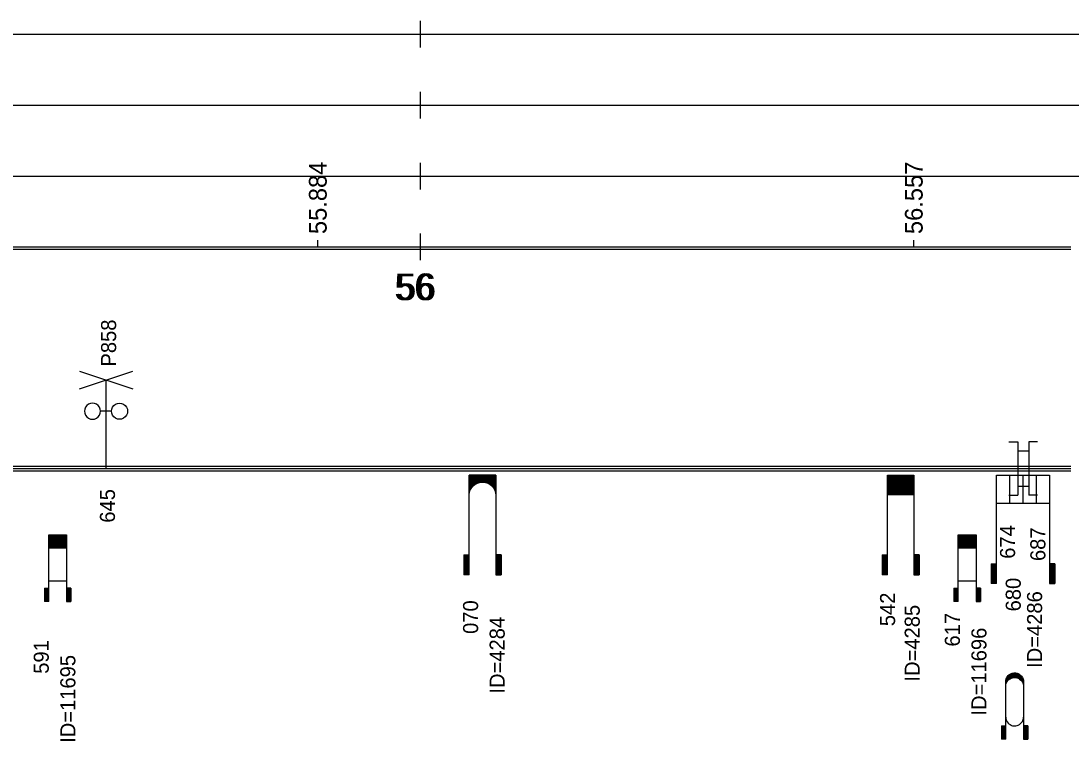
# Model space of a CAD drawing. Extents: x 2 to 10148, y 0 to 380.
# Drawn here: x 5856.4 to 5974.9, y 94.2 to 175.5 of the extents above; entities that cross this region are included whole.
import ezdxf

# ---------------------------------------------------------------- set-up
doc = ezdxf.new("R2010")
doc.units = 0
for name, color, linetype in [('CARA_S_OBJEKTY', 7, 'Continuous'), ('L_OBJEKTY_TEXT', 7, 'Continuous'), ('L_OBJEKTY_TVAR', 7, 'Continuous'), ('OBJEKTY_TEXT', 7, 'Continuous'), ('OBJEKTY_TVAR', 7, 'Continuous'), ('RYCHL_RASTR', 7, 'Continuous'), ('RYCHL_STAN', 7, 'Continuous'), ('STANIC_ZMEN_V', 7, 'Continuous')]:
    doc.layers.add(name, color=color, linetype=linetype)

msp = doc.modelspace()

# ---------------------------------------------------------------- linework, layer by layer
at = {"layer": 'CARA_S_OBJEKTY'}
for p, q in [((5128.6, 125.25), (5974.91, 125.25)), ((5128.6, 125), (5974.91, 125)), ((5128.6, 124.75), (5974.91, 124.75))]:
    msp.add_line(p, q, dxfattribs=at)
at = {"layer": 'L_OBJEKTY_TVAR'}
for p, q in [((5967.91, 128), (5968.91, 128)), ((5968.91, 128), (5968.91, 122)), ((5970.14, 128), (5970.14, 122)), ((5971.14, 128), (5970.14, 128)), ((5968.91, 127), (5970.14, 127)), ((5968.91, 123), (5970.14, 123)), ((5967.91, 122), (5968.91, 122)), ((5971.14, 122), (5970.14, 122))]:
    msp.add_line(p, q, dxfattribs=at)
at = {"layer": 'OBJEKTY_TVAR'}
for p, q in [((5863.03, 134), (5869.03, 136)), ((5863.03, 136), (5869.03, 134)), ((5866.03, 125), (5866.03, 135)), ((5863.6, 131.7), (5863.57, 131.46)), ((5863.69, 131.92), (5863.6, 131.7)), ((5863.84, 132.11), (5863.69, 131.92)), ((5864.03, 132.25), (5863.84, 132.11)), ((5864.25, 132.34), (5864.03, 132.25)), ((5864.48, 132.38), (5864.25, 132.34)), ((5864.72, 132.34), (5864.48, 132.38)), ((5864.94, 132.25), (5864.72, 132.34)), ((5865.13, 132.11), (5864.94, 132.25)), ((5865.27, 131.92), (5865.13, 132.11)), ((5865.36, 131.7), (5865.27, 131.92)), ((5865.39, 131.46), (5865.36, 131.7)), ((5866.63, 131.46), (5866.66, 131.7)), ((5866.66, 131.7), (5866.75, 131.92)), ((5866.75, 131.92), (5866.89, 132.11)), ((5866.89, 132.11), (5867.08, 132.25)), ((5867.08, 132.25), (5867.3, 132.34)), ((5867.3, 132.34), (5867.54, 132.38)), ((5867.54, 132.38), (5867.77, 132.34)), ((5867.77, 132.34), (5867.99, 132.25)), ((5867.99, 132.25), (5868.18, 132.11)), ((5868.18, 132.11), (5868.33, 131.92)), ((5868.33, 131.92), (5868.42, 131.7)), ((5868.42, 131.7), (5868.45, 131.46)), ((5863.57, 131.46), (5863.6, 131.23)), ((5863.6, 131.23), (5863.69, 131.01)), ((5863.69, 131.01), (5863.84, 130.82)), ((5863.84, 130.82), (5864.03, 130.67)), ((5864.03, 130.67), (5864.25, 130.58)), ((5864.25, 130.58), (5864.48, 130.55)), ((5864.48, 130.55), (5864.72, 130.58)), ((5864.72, 130.58), (5864.94, 130.67)), ((5864.94, 130.67), (5865.13, 130.82)), ((5865.13, 130.82), (5865.27, 131.01)), ((5865.27, 131.01), (5865.36, 131.23)), ((5865.36, 131.23), (5865.39, 131.46)), ((5866.63, 131.46), (5865.39, 131.46)), ((5866.66, 131.23), (5866.63, 131.46)), ((5866.75, 131.01), (5866.66, 131.23)), ((5866.89, 130.82), (5866.75, 131.01)), ((5867.08, 130.67), (5866.89, 130.82)), ((5867.3, 130.58), (5867.08, 130.67)), ((5867.54, 130.55), (5867.3, 130.58)), ((5867.77, 130.58), (5867.54, 130.55)), ((5867.99, 130.67), (5867.77, 130.58)), ((5868.18, 130.82), (5867.99, 130.67)), ((5868.33, 131.01), (5868.18, 130.82)), ((5868.42, 131.23), (5868.33, 131.01)), ((5868.45, 131.46), (5868.42, 131.23)), ((5907, 113), (5907, 124.25)), ((5910, 124.25), (5907, 124.25)), ((5907, 124.17), (5910, 124.17)), ((5907, 124.1), (5910, 124.1)), ((5907, 124.02), (5910, 124.02)), ((5907, 123.95), (5910, 123.95)), ((5907, 123.87), (5910, 123.87)), ((5907, 123.8), (5910, 123.8)), ((5907, 123.72), (5910, 123.72)), ((5907, 123.65), (5910, 123.65)), ((5907, 123.57), (5910, 123.57)), ((5907, 123.5), (5910, 123.5)), ((5907, 123.42), (5908.16, 123.42)), ((5907, 123.35), (5907.92, 123.35)), ((5907, 123.27), (5907.77, 123.27)), ((5907.64, 123.19), (5907.77, 123.27)), ((5907.77, 123.27), (5907.92, 123.35)), ((5907.92, 123.35), (5908.16, 123.42)), ((5908.16, 123.42), (5908.37, 123.46)), ((5908.37, 123.46), (5908.62, 123.46)), ((5908.62, 123.46), (5908.76, 123.44)), ((5908.76, 123.44), (5908.84, 123.42)), ((5908.84, 123.42), (5910, 123.42)), ((5908.84, 123.42), (5909.08, 123.35)), ((5909.08, 123.35), (5910, 123.35)), ((5909.08, 123.35), (5909.23, 123.27)), ((5909.23, 123.27), (5910, 123.27)), ((5909.23, 123.27), (5909.35, 123.2)), ((5910, 124.25), (5910, 113)), ((5954.19, 124.25), (5957.19, 124.25)), ((5954.19, 113), (5954.19, 124.25)), ((5954.19, 124.17), (5957.19, 124.17)), ((5954.19, 124.1), (5957.19, 124.1)), ((5954.19, 124.02), (5957.19, 124.02)), ((5954.19, 123.95), (5957.19, 123.95)), ((5954.19, 123.87), (5957.19, 123.87)), ((5954.19, 123.8), (5957.19, 123.8)), ((5954.19, 123.72), (5957.19, 123.72)), ((5954.19, 123.65), (5957.19, 123.65)), ((5954.19, 123.57), (5957.19, 123.57)), ((5954.19, 123.5), (5957.19, 123.5)), ((5954.19, 123.42), (5957.19, 123.42)), ((5954.19, 123.35), (5957.19, 123.35)), ((5954.19, 123.27), (5957.19, 123.27)), ((5957.19, 124.25), (5957.19, 113)), ((5966.5, 112), (5966.5, 124.25)), ((5966.5, 124.25), (5972.5, 124.25)), ((5968, 121.07), (5968, 124.25)), ((5969.5, 121.07), (5969.5, 124.25)), ((5971, 121.07), (5971, 124.25)), ((5972.5, 124.25), (5972.5, 112)), ((5907, 123.2), (5907.65, 123.2)), ((5907, 123.12), (5907.55, 123.12)), ((5907, 123.05), (5907.46, 123.05)), ((5907, 122.97), (5907.39, 122.97)), ((5907, 122.9), (5907.33, 122.9)), ((5907, 122.82), (5907.27, 122.82)), ((5907, 122.75), (5907.22, 122.75)), ((5907, 122.67), (5907.18, 122.67)), ((5907, 122.6), (5907.14, 122.6)), ((5907, 122.52), (5907.11, 122.52)), ((5907, 122.45), (5907.08, 122.45)), ((5907, 122.37), (5907.06, 122.37)), ((5907, 122.3), (5907.04, 122.3)), ((5907, 122.22), (5907.02, 122.22)), ((5907, 122.15), (5907.01, 122.15)), ((5907, 121.97), (5907.01, 122.11)), ((5907.01, 122.11), (5907.03, 122.28)), ((5907.03, 122.28), (5907.08, 122.46)), ((5907.08, 122.46), (5907.15, 122.61)), ((5907.15, 122.61), (5907.22, 122.75)), ((5907.22, 122.75), (5907.33, 122.9)), ((5907.33, 122.9), (5907.46, 123.05)), ((5907.46, 123.05), (5907.54, 123.12)), ((5907.54, 123.12), (5907.64, 123.19)), ((5909.35, 123.2), (5910, 123.2)), ((5909.35, 123.2), (5909.45, 123.12)), ((5909.45, 123.12), (5910, 123.12)), ((5909.45, 123.12), (5909.54, 123.05)), ((5909.54, 123.05), (5910, 123.05)), ((5909.54, 123.05), (5909.61, 122.97)), ((5909.61, 122.97), (5910, 122.97)), ((5909.61, 122.97), (5909.67, 122.9)), ((5909.67, 122.9), (5909.99, 122.9)), ((5909.67, 122.9), (5909.73, 122.82)), ((5909.73, 122.82), (5910, 122.82)), ((5909.73, 122.82), (5909.82, 122.67)), ((5909.78, 122.75), (5910, 122.75)), ((5909.82, 122.67), (5910, 122.67)), ((5909.82, 122.67), (5909.89, 122.52)), ((5909.86, 122.6), (5910, 122.6)), ((5909.89, 122.52), (5910, 122.52)), ((5909.89, 122.52), (5909.94, 122.37)), ((5909.92, 122.45), (5910, 122.45)), ((5909.94, 122.37), (5910, 122.37)), ((5909.94, 122.37), (5909.98, 122.22)), ((5909.96, 122.3), (5910, 122.3)), ((5909.98, 122.22), (5910, 122.22)), ((5909.98, 122.22), (5910, 121.97)), ((5909.99, 122.15), (5910, 122.15)), ((5954.19, 123.2), (5957.19, 123.2)), ((5954.19, 123.12), (5957.19, 123.12)), ((5954.19, 123.05), (5957.19, 123.05)), ((5954.19, 122.97), (5957.19, 122.97)), ((5954.19, 122.9), (5957.19, 122.9)), ((5954.19, 122.82), (5957.19, 122.82)), ((5954.19, 122.75), (5957.19, 122.75)), ((5954.19, 122.67), (5957.19, 122.67)), ((5954.19, 122.6), (5957.19, 122.6)), ((5954.19, 122.52), (5957.19, 122.52)), ((5954.19, 122.45), (5957.19, 122.45)), ((5954.19, 122.37), (5957.19, 122.37)), ((5954.19, 122.3), (5957.19, 122.3)), ((5954.19, 122.22), (5957.19, 122.22)), ((5954.19, 122.15), (5957.19, 122.15)), ((5954.19, 122.07), (5957.19, 122.07)), ((5966.5, 121.07), (5972.5, 121.07)), ((5859.55, 110), (5859.55, 117.5)), ((5859.55, 117.5), (5861.55, 117.5)), ((5859.55, 117.45), (5861.55, 117.45)), ((5859.55, 117.4), (5861.55, 117.4)), ((5859.55, 117.35), (5861.55, 117.35)), ((5861.55, 117.5), (5861.55, 110)), ((5962.19, 110), (5962.19, 117.5)), ((5962.19, 117.5), (5964.19, 117.5)), ((5962.19, 117.45), (5964.19, 117.45)), ((5962.19, 117.4), (5964.19, 117.4)), ((5962.19, 117.35), (5964.19, 117.35)), ((5964.19, 117.5), (5964.19, 110)), ((5859.55, 117.3), (5861.55, 117.3)), ((5859.55, 117.25), (5861.55, 117.25)), ((5859.55, 117.2), (5861.55, 117.2)), ((5859.55, 117.15), (5861.55, 117.15)), ((5859.55, 117.1), (5861.55, 117.1)), ((5859.55, 117.05), (5861.55, 117.05)), ((5859.55, 117), (5861.55, 117)), ((5859.55, 116.95), (5861.55, 116.95)), ((5859.55, 116.9), (5861.55, 116.9)), ((5859.55, 116.85), (5861.55, 116.85)), ((5859.55, 116.8), (5861.55, 116.8)), ((5859.55, 116.75), (5861.55, 116.75)), ((5859.55, 116.7), (5861.55, 116.7)), ((5859.55, 116.65), (5861.55, 116.65)), ((5859.55, 116.6), (5861.55, 116.6)), ((5859.55, 116.55), (5861.55, 116.55)), ((5859.55, 116.5), (5861.55, 116.5)), ((5859.55, 116.45), (5861.55, 116.45)), ((5859.55, 116.4), (5861.55, 116.4)), ((5859.55, 116.35), (5861.55, 116.35)), ((5859.55, 116.3), (5861.55, 116.3)), ((5859.55, 116.25), (5861.55, 116.25)), ((5859.55, 116.2), (5861.55, 116.2)), ((5859.55, 116.15), (5861.55, 116.15)), ((5962.19, 117.3), (5964.19, 117.3)), ((5962.19, 117.25), (5964.19, 117.25)), ((5962.19, 117.2), (5964.19, 117.2)), ((5962.19, 117.15), (5964.19, 117.15)), ((5962.19, 117.1), (5964.19, 117.1)), ((5962.19, 117.05), (5964.19, 117.05)), ((5962.19, 117), (5964.19, 117)), ((5962.19, 116.95), (5964.19, 116.95)), ((5962.19, 116.9), (5964.19, 116.9)), ((5962.19, 116.85), (5964.19, 116.85)), ((5962.19, 116.8), (5964.19, 116.8)), ((5962.19, 116.75), (5964.19, 116.75)), ((5962.19, 116.7), (5964.19, 116.7)), ((5962.19, 116.65), (5964.19, 116.65)), ((5962.19, 116.6), (5964.19, 116.6)), ((5962.19, 116.55), (5964.19, 116.55)), ((5962.19, 116.5), (5964.19, 116.5)), ((5962.19, 116.45), (5964.19, 116.45)), ((5962.19, 116.4), (5964.19, 116.4)), ((5962.19, 116.35), (5964.19, 116.35)), ((5962.19, 116.3), (5964.19, 116.3)), ((5962.19, 116.25), (5964.19, 116.25)), ((5962.19, 116.2), (5964.19, 116.2)), ((5962.19, 116.15), (5964.19, 116.15)), ((5859.55, 116.1), (5861.55, 116.1)), ((5859.55, 116.05), (5861.55, 116.05)), ((5906.4, 115.25), (5907, 115.25)), ((5906.4, 115.25), (5906.4, 113)), ((5906.47, 115.25), (5906.47, 113)), ((5906.55, 115.25), (5906.55, 113)), ((5906.62, 115.25), (5906.62, 113)), ((5906.7, 115.25), (5906.7, 113)), ((5906.77, 115.25), (5906.77, 113)), ((5906.85, 115.25), (5906.85, 113)), ((5906.92, 115.25), (5906.92, 113)), ((5910.6, 115.25), (5910, 115.25)), ((5910.08, 115.25), (5910.08, 113)), ((5910.15, 115.25), (5910.15, 113)), ((5910.23, 115.25), (5910.23, 113)), ((5910.3, 115.25), (5910.3, 113)), ((5910.38, 115.25), (5910.38, 113)), ((5910.45, 115.25), (5910.45, 113)), ((5910.53, 115.25), (5910.53, 113)), ((5910.6, 115.25), (5910.6, 113)), ((5953.59, 115.25), (5953.59, 113)), ((5953.59, 115.25), (5954.19, 115.25)), ((5953.66, 115.25), (5953.66, 113)), ((5953.74, 115.25), (5953.74, 113)), ((5953.81, 115.25), (5953.81, 113)), ((5953.89, 115.25), (5953.89, 113)), ((5953.96, 115.25), (5953.96, 113)), ((5954.04, 115.25), (5954.04, 113)), ((5954.11, 115.25), (5954.11, 113)), ((5957.79, 115.25), (5957.19, 115.25)), ((5957.27, 115.25), (5957.27, 113)), ((5957.34, 115.25), (5957.34, 113)), ((5957.42, 115.25), (5957.42, 113)), ((5957.49, 115.25), (5957.49, 113)), ((5957.57, 115.25), (5957.57, 113)), ((5957.64, 115.25), (5957.64, 113)), ((5957.72, 115.25), (5957.72, 113)), ((5957.79, 115.25), (5957.79, 113)), ((5962.19, 116.1), (5964.19, 116.1)), ((5962.19, 116.05), (5964.19, 116.05)), ((5965.9, 114.25), (5965.9, 112)), ((5965.9, 114.25), (5966.5, 114.25)), ((5965.97, 114.25), (5965.97, 112)), ((5966.05, 114.25), (5966.05, 112)), ((5966.12, 114.25), (5966.12, 112)), ((5966.2, 114.25), (5966.2, 112)), ((5966.27, 114.25), (5966.27, 112)), ((5966.35, 114.25), (5966.35, 112)), ((5966.42, 114.25), (5966.42, 112)), ((5973.1, 114.25), (5972.5, 114.25)), ((5972.58, 114.25), (5972.58, 112)), ((5972.65, 114.25), (5972.65, 112)), ((5972.73, 114.25), (5972.73, 112)), ((5972.8, 114.25), (5972.8, 112)), ((5972.88, 114.25), (5972.88, 112)), ((5972.95, 114.25), (5972.95, 112)), ((5973.03, 114.25), (5973.03, 112)), ((5973.1, 114.25), (5973.1, 112)), ((5907, 113), (5906.4, 113)), ((5910, 113), (5910.6, 113)), ((5954.19, 113), (5953.59, 113)), ((5957.19, 113), (5957.79, 113)), ((5859.05, 111.5), (5859.55, 111.5)), ((5859.05, 111.5), (5859.05, 110)), ((5859.1, 111.5), (5859.1, 110)), ((5859.15, 111.5), (5859.15, 110)), ((5859.2, 111.5), (5859.2, 110)), ((5859.25, 111.5), (5859.25, 110)), ((5859.3, 111.5), (5859.3, 110)), ((5859.35, 111.5), (5859.35, 110)), ((5859.4, 111.5), (5859.4, 110)), ((5859.45, 111.5), (5859.45, 110)), ((5859.5, 111.5), (5859.5, 110)), ((5859.55, 112.31), (5861.55, 112.31)), ((5862.05, 111.5), (5861.55, 111.5)), ((5861.6, 111.5), (5861.6, 110)), ((5861.65, 111.5), (5861.65, 110)), ((5861.7, 111.5), (5861.7, 110)), ((5861.75, 111.5), (5861.75, 110)), ((5861.8, 111.5), (5861.8, 110)), ((5861.85, 111.5), (5861.85, 110)), ((5861.9, 111.5), (5861.9, 110)), ((5861.95, 111.5), (5861.95, 110)), ((5862, 111.5), (5862, 110)), ((5862.05, 111.5), (5862.05, 110)), ((5961.69, 111.5), (5962.19, 111.5)), ((5961.69, 111.5), (5961.69, 110)), ((5961.74, 111.5), (5961.74, 110)), ((5961.79, 111.5), (5961.79, 110)), ((5961.84, 111.5), (5961.84, 110)), ((5961.89, 111.5), (5961.89, 110)), ((5961.94, 111.5), (5961.94, 110)), ((5961.99, 111.5), (5961.99, 110)), ((5962.04, 111.5), (5962.04, 110)), ((5962.09, 111.5), (5962.09, 110)), ((5962.14, 111.5), (5962.14, 110)), ((5962.19, 112.31), (5964.19, 112.31)), ((5964.69, 111.5), (5964.19, 111.5)), ((5964.24, 111.5), (5964.24, 110)), ((5964.29, 111.5), (5964.29, 110)), ((5964.34, 111.5), (5964.34, 110)), ((5964.39, 111.5), (5964.39, 110)), ((5964.44, 111.5), (5964.44, 110)), ((5964.49, 111.5), (5964.49, 110)), ((5964.54, 111.5), (5964.54, 110)), ((5964.59, 111.5), (5964.59, 110)), ((5964.64, 111.5), (5964.64, 110)), ((5964.69, 111.5), (5964.69, 110)), ((5966.5, 112), (5965.9, 112)), ((5972.5, 112), (5973.1, 112)), ((5859.55, 110), (5859.05, 110)), ((5861.55, 110), (5862.05, 110)), ((5962.19, 110), (5961.69, 110)), ((5964.19, 110), (5964.69, 110)), ((5968.19, 101.87), (5968.31, 101.91)), ((5968.31, 101.91), (5968.45, 101.93)), ((5968.45, 101.93), (5968.56, 101.94)), ((5968.56, 101.94), (5968.69, 101.93)), ((5968.69, 101.93), (5968.82, 101.9)), ((5967.55, 100.94), (5967.56, 101.09)), ((5967.55, 100.99), (5967.73, 100.99)), ((5967.55, 94.44), (5967.55, 100.94)), ((5967.55, 100.94), (5967.7, 100.94)), ((5967.55, 100.89), (5967.67, 100.89)), ((5967.55, 100.84), (5967.64, 100.84)), ((5967.55, 100.79), (5967.62, 100.79)), ((5967.55, 100.74), (5967.6, 100.74)), ((5967.56, 101.09), (5967.6, 101.25)), ((5967.56, 101.09), (5967.81, 101.09)), ((5967.56, 101.04), (5967.77, 101.04)), ((5967.57, 101.14), (5967.86, 101.14)), ((5967.58, 101.19), (5967.92, 101.19)), ((5967.6, 101.25), (5967.66, 101.39)), ((5967.6, 101.24), (5967.98, 101.24)), ((5967.6, 100.72), (5967.66, 100.87)), ((5967.61, 101.29), (5968.06, 101.29)), ((5967.63, 101.34), (5968.17, 101.34)), ((5967.66, 101.39), (5967.72, 101.5)), ((5967.66, 101.39), (5968.32, 101.39)), ((5967.66, 100.87), (5967.72, 100.97)), ((5967.68, 101.44), (5969.42, 101.44)), ((5967.71, 101.49), (5969.39, 101.49)), ((5967.72, 101.5), (5967.81, 101.62)), ((5967.72, 100.97), (5967.81, 101.09)), ((5967.75, 101.54), (5969.35, 101.54)), ((5967.79, 101.59), (5969.31, 101.59)), ((5967.81, 101.62), (5967.9, 101.7)), ((5967.81, 101.09), (5967.9, 101.18)), ((5967.84, 101.64), (5969.26, 101.64)), ((5967.89, 101.69), (5969.21, 101.69)), ((5967.9, 101.7), (5968.03, 101.79)), ((5967.9, 101.18), (5968.03, 101.27)), ((5967.95, 101.74), (5969.15, 101.74)), ((5968.02, 101.79), (5969.08, 101.79)), ((5968.03, 101.79), (5968.16, 101.86)), ((5968.03, 101.27), (5968.16, 101.34)), ((5968.11, 101.84), (5968.99, 101.84)), ((5968.16, 101.86), (5968.19, 101.87)), ((5968.16, 101.34), (5968.19, 101.35)), ((5968.19, 101.35), (5968.31, 101.39)), ((5968.24, 101.89), (5968.86, 101.89)), ((5968.31, 101.39), (5968.45, 101.41)), ((5968.45, 101.41), (5968.56, 101.42)), ((5968.56, 101.42), (5968.69, 101.41)), ((5968.69, 101.41), (5968.82, 101.38)), ((5968.78, 101.39), (5969.44, 101.39)), ((5968.82, 101.9), (5968.93, 101.87)), ((5968.82, 101.38), (5968.93, 101.34)), ((5968.93, 101.87), (5969.04, 101.81)), ((5968.93, 101.34), (5969.04, 101.29)), ((5968.93, 101.34), (5969.47, 101.34)), ((5969.04, 101.81), (5969.11, 101.76)), ((5969.04, 101.29), (5969.49, 101.29)), ((5969.04, 101.29), (5969.11, 101.24)), ((5969.11, 101.76), (5969.26, 101.65)), ((5969.11, 101.24), (5969.26, 101.12)), ((5969.12, 101.24), (5969.5, 101.24)), ((5969.18, 101.19), (5969.52, 101.19)), ((5969.24, 101.14), (5969.53, 101.14)), ((5969.26, 101.65), (5969.34, 101.55)), ((5969.26, 101.12), (5969.34, 101.03)), ((5969.29, 101.09), (5969.54, 101.09)), ((5969.33, 101.04), (5969.54, 101.04)), ((5969.34, 101.55), (5969.43, 101.42)), ((5969.34, 101.03), (5969.43, 100.9)), ((5969.37, 100.99), (5969.55, 100.99)), ((5969.4, 100.94), (5969.55, 100.94)), ((5969.43, 101.42), (5969.47, 101.33)), ((5969.43, 100.9), (5969.47, 100.81)), ((5969.43, 100.89), (5969.55, 100.89)), ((5969.46, 100.84), (5969.55, 100.84)), ((5969.47, 101.33), (5969.51, 101.21)), ((5969.47, 100.81), (5969.51, 100.68)), ((5969.48, 100.79), (5969.55, 100.79)), ((5969.5, 100.74), (5969.55, 100.74)), ((5969.51, 101.21), (5969.54, 101.09)), ((5969.54, 101.09), (5969.55, 101)), ((5969.55, 101), (5969.55, 100.94)), ((5969.55, 100.94), (5969.55, 94.44)), ((5967.55, 100.69), (5967.59, 100.69)), ((5967.55, 100.64), (5967.58, 100.64)), ((5967.55, 100.59), (5967.57, 100.59)), ((5967.55, 100.42), (5967.56, 100.57)), ((5967.55, 100.54), (5967.56, 100.54)), ((5967.56, 100.57), (5967.6, 100.72)), ((5969.51, 100.69), (5969.55, 100.69)), ((5969.51, 100.68), (5969.54, 100.57)), ((5969.52, 100.64), (5969.55, 100.64)), ((5969.53, 100.59), (5969.55, 100.59)), ((5969.54, 100.57), (5969.55, 100.47)), ((5969.54, 100.54), (5969.55, 100.54)), ((5969.55, 100.47), (5969.55, 100.42)), ((5967.55, 96.94), (5967.56, 96.79)), ((5967.56, 96.79), (5967.6, 96.64)), ((5967.6, 96.64), (5967.66, 96.49)), ((5967.66, 96.49), (5967.72, 96.39)), ((5967.72, 96.39), (5967.81, 96.27)), ((5967.81, 96.27), (5967.9, 96.18)), ((5967.9, 96.18), (5968.03, 96.09)), ((5968.03, 96.09), (5968.16, 96.02)), ((5968.16, 96.02), (5968.19, 96.01)), ((5968.19, 96.01), (5968.31, 95.97)), ((5968.82, 95.98), (5968.93, 96.02)), ((5968.93, 96.02), (5969.04, 96.07)), ((5969.04, 96.07), (5969.11, 96.12)), ((5969.11, 96.12), (5969.26, 96.24)), ((5969.26, 96.24), (5969.34, 96.34)), ((5969.34, 96.34), (5969.43, 96.46)), ((5969.43, 96.46), (5969.47, 96.55)), ((5969.47, 96.55), (5969.51, 96.68)), ((5969.51, 96.68), (5969.54, 96.79)), ((5969.54, 96.79), (5969.55, 96.89)), ((5969.55, 96.89), (5969.55, 96.94)), ((5967.05, 95.94), (5967.55, 95.94)), ((5967.05, 95.94), (5967.05, 94.44)), ((5967.1, 95.94), (5967.1, 94.44)), ((5967.15, 95.94), (5967.15, 94.44)), ((5967.2, 95.94), (5967.2, 94.44)), ((5967.25, 95.94), (5967.25, 94.44)), ((5967.3, 95.94), (5967.3, 94.44)), ((5967.35, 95.94), (5967.35, 94.44)), ((5967.4, 95.94), (5967.4, 94.44)), ((5967.45, 95.94), (5967.45, 94.44)), ((5967.5, 95.94), (5967.5, 94.44)), ((5968.31, 95.97), (5968.45, 95.95)), ((5968.45, 95.95), (5968.56, 95.94)), ((5968.56, 95.94), (5968.69, 95.95)), ((5968.69, 95.95), (5968.82, 95.98)), ((5970.05, 95.94), (5969.55, 95.94)), ((5969.6, 95.94), (5969.6, 94.44)), ((5969.65, 95.94), (5969.65, 94.44)), ((5969.7, 95.94), (5969.7, 94.44)), ((5969.75, 95.94), (5969.75, 94.44)), ((5969.8, 95.94), (5969.8, 94.44)), ((5969.85, 95.94), (5969.85, 94.44)), ((5969.9, 95.94), (5969.9, 94.44)), ((5969.95, 95.94), (5969.95, 94.44)), ((5970, 95.94), (5970, 94.44)), ((5970.05, 95.94), (5970.05, 94.44)), ((5967.55, 94.44), (5967.05, 94.44)), ((5969.55, 94.44), (5970.05, 94.44))]:
    msp.add_line(p, q, dxfattribs=at)
at = {"layer": 'RYCHL_RASTR'}
for p, q in [((5901.49, 172.5), (5901.49, 175.5)), ((5122.71, 174), (5974.23, 174)), ((5971.78, 174), (6873.11, 174)), ((5901.49, 164.5), (5901.49, 167.5)), ((5122.69, 166), (5974.36, 166)), ((5971.77, 166), (6873.11, 166)), ((5901.49, 156.5), (5901.49, 159.5)), ((5122.67, 158), (5974.55, 158)), ((5971.78, 158), (6873.11, 158)), ((5901.49, 148.5), (5901.49, 151.5)), ((5128.6, 150), (5974.91, 150)), ((5128.6, 149.75), (5974.91, 149.75))]:
    msp.add_line(p, q, dxfattribs=at)
at = {"layer": 'STANIC_ZMEN_V'}
for p, q in [((5889.91, 150), (5889.91, 150.75)), ((5957.17, 150), (5957.17, 150.75))]:
    msp.add_line(p, q, dxfattribs=at)

# ---------------------------------------------------------------- texts
at = {"layer": 'L_OBJEKTY_TEXT'}
for s, p in [('674', (5968.6, 114.81)), ('687', (5972.02, 114.55))]:
    msp.add_text(s, height=1.7, rotation=90, dxfattribs=at).set_placement(p)
at = {"layer": 'OBJEKTY_TEXT'}
for s, p in [('P858', (5867.15, 136.5)), ('645', (5867.02, 118.88)), ('680', (5969.24, 108.87)), ('542', (5955.06, 107.2)), ('ID=4286', (5971.65, 102.49)), ('070', (5908, 106.33)), ('ID=4285', (5957.84, 100.95)), ('ID=4284', (5911, 99.59)), ('617', (5962.37, 104.9)), ('ID=11696', (5965.37, 97.11)), ('591', (5859.55, 101.83)), ('ID=11695', (5862.55, 94.03))]:
    msp.add_text(s, height=1.7, rotation=90, dxfattribs=at).set_placement(p)
at = {"layer": 'RYCHL_STAN'}
for p in [(5898.55, 144), (5898.8, 144)]:
    msp.add_text('56', height=3, dxfattribs=at).set_placement(p)
at = {"layer": 'STANIC_ZMEN_V'}
for s, p in [('55.884', (5890.91, 151.45)), ('56.557', (5958.17, 151.45))]:
    msp.add_text(s, height=2, rotation=90, dxfattribs=at).set_placement(p)

doc.saveas('drawing.dxf')
